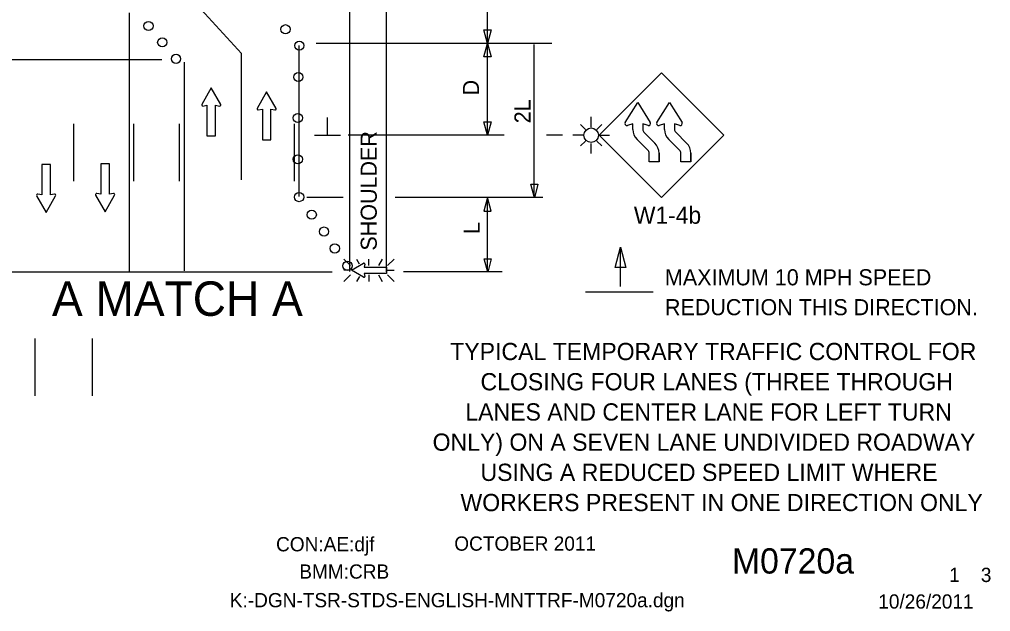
# Model space of a CAD drawing. Extents: x 16726 to 19504, y 5932 to 7446.
# Drawn here: x 16978.9 to 17401.8, y 5931.8 to 6189.6 of the extents above; entities that cross this region are included whole.
import ezdxf

# ---------------------------------------------------------------- set-up
doc = ezdxf.new("R2010")
doc.units = 0
for name, color, linetype in [('ALI_LEGAL_EX', 7, 'Continuous'), ('BORDER_SIGNAL_WO', 7, 'Continuous'), ('MT_SCRATCH_LEVEL_E', 7, 'Continuous'), ('PAVT_EDGE_EX', 7, 'Continuous'), ('TRAFFIC_SIGNS_PR', 7, 'Continuous'), ('TYPICAL_TEXT_DIMEN_PR', 7, 'Continuous')]:
    doc.layers.add(name, color=color, linetype=linetype)

msp = doc.modelspace()

# ---------------------------------------------------------------- linework, layer by layer
at = {"layer": 'ALI_LEGAL_EX'}
for points in [[(17075.62, 6119.76), (17075.62, 6174.72)], [(17002.71, 6119.12), (17002.71, 6144.12)], [(17028.71, 6119.12), (17028.71, 6144.12)], [(17048.71, 6119.12), (17048.71, 6144.12)], [(17098.71, 6119.12), (17098.71, 6144.12)]]:
    msp.add_lwpolyline(points, dxfattribs=at)
at = {"layer": 'MT_SCRATCH_LEVEL_E'}
for p, q in [((17062.47, 6159.81), (17058.36, 6152.57)), ((17062.47, 6159.81), (17058.36, 6152.57)), ((17066.62, 6152.57), (17062.47, 6159.81)), ((17066.62, 6152.57), (17062.47, 6159.81)), ((17086.57, 6158.1), (17082.46, 6150.86)), ((17086.57, 6158.1), (17082.46, 6150.86)), ((17090.72, 6150.86), (17086.57, 6158.1)), ((17090.72, 6150.86), (17086.57, 6158.1)), ((17058.85, 6151.89), (17060.62, 6152.2)), ((17058.85, 6151.89), (17060.62, 6152.2)), ((17060.62, 6152.2), (17060.62, 6138.94)), ((17060.62, 6152.2), (17060.62, 6138.94)), ((17064.36, 6138.94), (17064.36, 6152.2)), ((17064.36, 6152.2), (17066.14, 6151.89)), ((17064.36, 6138.94), (17064.36, 6152.2)), ((17064.36, 6152.2), (17066.14, 6151.89)), ((17082.94, 6150.17), (17084.72, 6150.49)), ((17082.94, 6150.17), (17084.72, 6150.49)), ((17084.72, 6150.49), (17084.72, 6137.23)), ((17084.72, 6150.49), (17084.72, 6137.23)), ((17088.46, 6137.23), (17088.46, 6150.49)), ((17088.46, 6150.49), (17090.24, 6150.17)), ((17088.46, 6137.23), (17088.46, 6150.49)), ((17088.46, 6150.49), (17090.24, 6150.17)), ((17060.62, 6138.94), (17064.36, 6138.94)), ((17060.62, 6138.94), (17064.36, 6138.94)), ((17084.72, 6137.23), (17088.46, 6137.23)), ((17084.72, 6137.23), (17088.46, 6137.23)), ((16992.45, 6126.46), (16988.71, 6126.46)), ((16988.71, 6126.46), (16988.71, 6113.2)), ((16992.45, 6126.46), (16988.71, 6126.46)), ((16988.71, 6126.46), (16988.71, 6113.2)), ((16992.45, 6113.2), (16992.45, 6126.46)), ((16992.45, 6113.2), (16992.45, 6126.46)), ((17018.13, 6126.72), (17014.39, 6126.72)), ((17014.39, 6126.72), (17014.39, 6113.46)), ((17018.13, 6126.72), (17014.39, 6126.72)), ((17014.39, 6126.72), (17014.39, 6113.46)), ((17018.13, 6113.46), (17018.13, 6126.72)), ((17018.13, 6113.46), (17018.13, 6126.72)), ((16986.45, 6112.84), (16990.6, 6105.6)), ((16986.45, 6112.84), (16990.6, 6105.6)), ((16988.71, 6113.2), (16986.93, 6113.52)), ((16988.71, 6113.2), (16986.93, 6113.52)), ((16990.6, 6105.6), (16994.71, 6112.84)), ((16990.6, 6105.6), (16994.71, 6112.84)), ((16994.23, 6113.52), (16992.45, 6113.2)), ((16994.23, 6113.52), (16992.45, 6113.2)), ((17012.13, 6113.09), (17016.28, 6105.85)), ((17012.13, 6113.09), (17016.28, 6105.85)), ((17014.39, 6113.46), (17012.61, 6113.78)), ((17014.39, 6113.46), (17012.61, 6113.78)), ((17016.28, 6105.85), (17020.39, 6113.09)), ((17016.28, 6105.85), (17020.39, 6113.09)), ((17019.91, 6113.78), (17018.13, 6113.46)), ((17019.91, 6113.78), (17018.13, 6113.46))]:
    msp.add_line(p, q, dxfattribs=at)
for centre, start, end in [((17058.77, 6152.35), 150.4248, 279.9638), ((17058.77, 6152.35), 150.4248, 279.9638), ((17066.21, 6152.35), 260.0362, 29.7731), ((17066.21, 6152.35), 260.0362, 29.7731), ((17082.87, 6150.63), 150.4248, 279.9638), ((17082.87, 6150.63), 150.4248, 279.9638), ((17090.31, 6150.63), 260.0362, 29.7731), ((17090.31, 6150.63), 260.0362, 29.7731), ((16986.86, 6113.06), 80.0362, 209.7731), ((16986.86, 6113.06), 80.0362, 209.7731), ((16994.3, 6113.06), 330.4248, 99.9638), ((16994.3, 6113.06), 330.4248, 99.9638), ((17012.54, 6113.32), 80.0362, 209.7731), ((17012.54, 6113.32), 80.0362, 209.7731), ((17019.98, 6113.32), 330.4248, 99.9638), ((17019.98, 6113.32), 330.4248, 99.9638)]:
    msp.add_arc(centre, 0.463, start, end, dxfattribs=at)
at = {"layer": 'PAVT_EDGE_EX'}
for p, q in [((17122.71, 6865.32), (17122.71, 6079.93)), ((17138.71, 6865.32), (17138.71, 6112.72)), ((17026.71, 6192.44), (17026.71, 6079.72)), ((17050.71, 6170.95), (17050.71, 6080.14)), ((17138.71, 6112.72), (17138.71, 6079.72))]:
    msp.add_line(p, q, dxfattribs=at)
for points in [[(16985.78, 6025.74), (16985.78, 6050.74)], [(16985.78, 6025.74), (16985.78, 6050.74)], [(17010.78, 6025.74), (17010.78, 6050.74)], [(17010.78, 6025.74), (17010.78, 6050.74)]]:
    msp.add_lwpolyline(points, dxfattribs=at)
at = {"layer": 'TRAFFIC_SIGNS_PR'}
for p, q in [((17231.4, 6139.23), (17258.55, 6166.38)), ((17258.55, 6166.38), (17285.7, 6139.23)), ((17227.91, 6142.73), (17227.91, 6147.23)), ((17225.4, 6141.69), (17223.29, 6143.8)), ((17230.43, 6141.69), (17232.53, 6143.8)), ((17255.62, 6135.76), (17250.91, 6140.47)), ((17250.91, 6140.47), (17255.62, 6135.76)), ((17269.42, 6135.76), (17264.7, 6140.47)), ((17264.7, 6140.47), (17269.42, 6135.76)), ((17224.76, 6139.18), (17219.92, 6139.18)), ((17225.4, 6136.66), (17223.29, 6134.56)), ((17230.43, 6136.66), (17232.53, 6134.56)), ((17231.07, 6139.18), (17235.95, 6139.18)), ((17258.55, 6112.07), (17231.4, 6139.23)), ((17252.57, 6132.71), (17247.86, 6137.42)), ((17252.57, 6132.71), (17247.86, 6137.42)), ((17285.7, 6139.23), (17258.55, 6112.07)), ((17266.37, 6132.71), (17261.65, 6137.42)), ((17266.36, 6132.71), (17261.65, 6137.42)), ((17227.91, 6131.21), (17227.91, 6135.62)), ((17253.17, 6127.64), (17253.17, 6131.34)), ((17257.49, 6127.64), (17253.17, 6127.64)), ((17257.49, 6127.64), (17257.49, 6131.34)), ((17266.97, 6127.64), (17266.97, 6131.34)), ((17271.28, 6127.64), (17266.97, 6127.64)), ((17271.28, 6127.64), (17271.28, 6131.34)), ((17120.25, 6085.24), (17123.07, 6082.42)), ((17125.69, 6085.24), (17126.89, 6083.15)), ((17131.15, 6082.42), (17131.15, 6085.24)), ((17136.94, 6085.24), (17135.31, 6082.42)), ((17139.24, 6082.42), (17142.06, 6085.24)), ((17123.07, 6080.39), (17120.25, 6080.39)), ((17120.25, 6075.54), (17123.07, 6078.36)), ((17126.97, 6077.72), (17125.71, 6075.54)), ((17131.15, 6078.36), (17131.15, 6075.54)), ((17135.29, 6078.36), (17136.92, 6075.54)), ((17139.24, 6080.39), (17142.06, 6080.39)), ((17139.24, 6078.36), (17142.06, 6075.54))]:
    msp.add_line(p, q, dxfattribs=at)
for points in [[(17242.7, 6144.75), (17248.18, 6153.36), (17253.66, 6144.75)], [(17242.7, 6144.75), (17248.18, 6153.36), (17253.66, 6144.75)], [(17256.5, 6144.75), (17261.98, 6153.36), (17267.46, 6144.75)], [(17256.5, 6144.75), (17261.98, 6153.36), (17267.46, 6144.75)], [(17246.03, 6141.73), (17246.03, 6144.1), (17243.66, 6143.45)], [(17246.03, 6141.73), (17246.03, 6144.1), (17243.66, 6143.45)], [(17252.7, 6143.45), (17250.34, 6144.1), (17250.35, 6141.8)], [(17252.7, 6143.45), (17251.87, 6143.68), (17250.34, 6144.1), (17250.35, 6141.8)], [(17259.83, 6141.73), (17259.82, 6144.1), (17257.46, 6143.45)], [(17259.83, 6141.73), (17259.82, 6144.1), (17257.46, 6143.45)], [(17266.5, 6143.45), (17264.14, 6144.1), (17264.14, 6141.8)], [(17266.5, 6143.45), (17265.67, 6143.68), (17264.14, 6144.1), (17264.14, 6141.8)], [(17257.49, 6131.34), (17257.49, 6127.64), (17253.17, 6127.64), (17253.17, 6131.34)], [(17271.29, 6131.34), (17271.28, 6127.64), (17266.97, 6127.64), (17266.97, 6131.34)], [(17128.83, 6077.38), (17123.52, 6080.39), (17128.83, 6083.43)], [(17129.33, 6083.07), (17129.1, 6081.78), (17138.82, 6081.78), (17138.82, 6079.03), (17129.1, 6079.03), (17129.33, 6077.73)]]:
    msp.add_lwpolyline(points, dxfattribs=at)
for centre, radius in [((17035.14, 6186.72), 2), ((17094.81, 6185.3), 2), ((17041.14, 6179.58), 2), ((17100.81, 6178.16), 2), ((17047.14, 6172.44), 2), ((17100.41, 6164.49), 2), ((17100.19, 6146.69), 2), ((17227.91, 6139.18), 3.15), ((17100.19, 6128.69), 2), ((17100.73, 6112.25), 2), ((17106.24, 6104.59), 2), ((17111.58, 6097.24), 2), ((17116.26, 6089.9), 2), ((17121.82, 6082.34), 2)]:
    msp.add_circle(centre, radius, dxfattribs=at)
for centre, radius, start, end in [((17243.43, 6144.29), 0.866, 147.7292, 285.3172), ((17243.43, 6144.29), 0.866, 147.7196, 285.3201), ((17233.59, 6150.54), 10.8, 327.5335, 327.5431), ((17252.93, 6144.28), 0.866, 254.6148, 32.4712), ((17252.93, 6144.28), 0.864, 254.6014, 32.4796), ((17257.23, 6144.29), 0.866, 147.7292, 285.3172), ((17257.23, 6144.29), 0.866, 147.7196, 285.3201), ((17247.39, 6150.54), 10.8, 327.5335, 327.5431), ((17266.73, 6144.28), 0.864, 254.6014, 32.4796), ((17266.73, 6144.28), 0.866, 254.6148, 32.4712), ((17246.52, 6133.03), 10.8, 105.3192, 105.32), ((17252.2, 6141.8), 6.17, 180.6181, 225.7875), ((17252.2, 6141.8), 6.17, 180.6245, 225.2313), ((17252.2, 6141.8), 1.85, 180, 225.7875), ((17252.2, 6141.8), 1.85, 179.8762, 225.7877), ((17260.31, 6133.03), 10.8, 105.3192, 105.32), ((17265.99, 6141.8), 6.17, 180.6181, 225.7875), ((17265.99, 6141.8), 6.17, 180.6245, 225.2313), ((17265.99, 6141.8), 1.85, 180, 225.7875), ((17265.99, 6141.8), 1.85, 179.8762, 225.7877), ((17251.32, 6131.34), 1.85, 0, 47.628), ((17251.32, 6131.34), 1.85, 0, 45.7875), ((17251.32, 6131.34), 6.17, 0, 45.7875), ((17251.32, 6131.34), 6.17, 0, 45.7875), ((17251.32, 6131.34), 6.17, 0, 45.7883), ((17265.12, 6131.34), 1.85, 0, 47.628), ((17265.12, 6131.34), 1.85, 0, 45.7875), ((17265.12, 6131.34), 6.17, 0, 45.7875), ((17265.12, 6131.34), 6.17, 0, 45.7875), ((17265.12, 6131.34), 6.17, 0, 45.7883), ((17128.99, 6083.13), 0.341, 350.0407, 118.5167), ((17128.99, 6077.67), 0.341, 241.1084, 9.2692)]:
    msp.add_arc(centre, radius, start, end, dxfattribs=at)
at = {"layer": 'TYPICAL_TEXT_DIMEN_PR'}
for p, q in [((17182.71, 6179.17), (17182.71, 6267.12)), ((17002.71, 6254.65), (17075.64, 6174.71)), ((17182.74, 6179.15), (17181.17, 6185.02)), ((17181.17, 6185.02), (17182.74, 6185.02)), ((17182.74, 6185.02), (17184.31, 6185.02)), ((17184.31, 6185.02), (17182.74, 6179.15)), ((17100.6, 6178.28), (17100.6, 6112.56)), ((17210.8, 6179.15), (17108.13, 6179.15)), ((17181.17, 6173.31), (17182.74, 6179.17)), ((17182.74, 6179.17), (17184.31, 6173.31)), ((17182.75, 6139.15), (17182.75, 6179.15)), ((17203.14, 6112.66), (17203.14, 6178.73)), ((16893.7, 6172.07), (17040.9, 6172.07)), ((17182.74, 6173.31), (17181.17, 6173.31)), ((17184.31, 6173.31), (17182.74, 6173.31)), ((17113.12, 6139.1), (17113.12, 6146.88)), ((17182.75, 6139.15), (17181.18, 6145.01)), ((17181.18, 6145.01), (17182.75, 6145.01)), ((17182.75, 6145.01), (17184.32, 6145.01)), ((17184.32, 6145.01), (17182.75, 6139.15)), ((17118.74, 6139.1), (17107.49, 6139.1)), ((17189.98, 6139.15), (17122.03, 6139.15)), ((17215.4, 6139.15), (17208.49, 6139.15)), ((17203.18, 6111.98), (17201.61, 6117.84)), ((17201.61, 6117.84), (17203.18, 6117.84)), ((17203.18, 6117.84), (17204.75, 6117.84)), ((17204.75, 6117.84), (17203.18, 6111.98)), ((17119.91, 6112.01), (17104.16, 6112.01)), ((17206.84, 6112.01), (17142.6, 6112.01)), ((17182.75, 6112.01), (17181.18, 6106.15)), ((17182.71, 6090.25), (17182.71, 6111.5)), ((17182.73, 6079.65), (17182.73, 6111.93)), ((17184.32, 6106.15), (17182.75, 6112.01)), ((17181.18, 6106.15), (17182.75, 6106.15)), ((17182.75, 6106.15), (17184.32, 6106.15)), ((17238.32, 6081.66), (17240.67, 6090.45)), ((17240.67, 6073.33), (17240.67, 6090.45)), ((17240.67, 6090.45), (17243.03, 6081.66)), ((17182.86, 6079.57), (17181.29, 6085.43)), ((17181.29, 6085.43), (17182.86, 6085.43)), ((17182.86, 6085.43), (17184.43, 6085.43)), ((17184.43, 6085.43), (17182.86, 6079.57)), ((17240.67, 6081.66), (17238.32, 6081.66)), ((17243.03, 6081.66), (17240.67, 6081.66)), ((16927.17, 6079.72), (17115.16, 6079.72)), ((17189.17, 6079.72), (17146.21, 6079.72)), ((17254.85, 6070.83), (17225.41, 6070.83))]:
    msp.add_line(p, q, dxfattribs=at)

# ---------------------------------------------------------------- texts
at = {"layer": 'BORDER_SIGNAL_WO'}
for s, height, p in [('TYPICAL TEMPORARY TRAFFIC CONTROL FOR ', 7.5024, (17166.54, 6041.29)), ('CLOSING FOUR LANES (THREE THROUGH ', 7.5024, (17179.72, 6028.14)), ('LANES AND CENTER LANE FOR LEFT TURN ', 7.5024, (17173.13, 6014.99)), ('ONLY) ON A SEVEN LANE UNDIVIDED ROADWAY ', 7.5024, (17158.86, 6001.84)), ('USING A REDUCED SPEED LIMIT WHERE ', 7.5024, (17179.72, 5988.7)), ('WORKERS PRESENT IN ONE DIRECTION ONLY', 7.5024, (17171, 5975.55)), ('CON:AE:djf', 6.2, (17090.69, 5958.06)), ('    OCTOBER 2011    ', 6.2, (17159.08, 5958.34)), ('    M0720a   ', 11, (17272.86, 5948.38)), ('BMM:CRB   ', 6.2, (17100.81, 5946.17)), (' 1    3 ', 6.2, (17381.45, 5944.7)), ('K:-DGN-TSR-STDS-ENGLISH-MNTTRF-M0720a.dgn        ', 6.2, (17070.55, 5933.71)), ('10/26/2011    ', 6.2, (17352.93, 5933.13))]:
    msp.add_text(s, height=height, dxfattribs=at).set_placement(p)
at = {"layer": 'TRAFFIC_SIGNS_PR'}
msp.add_text('W1-4b', height=7.44, dxfattribs=at).set_placement((17246.5, 6100.63))
at = {"layer": 'TYPICAL_TEXT_DIMEN_PR'}
for s, p in [('D', (17179.06, 6156.5)), ('2L', (17201.5, 6144.35)), ('SHOULDER', (17134.55, 6088.95)), ('L', (17179.37, 6096.15))]:
    msp.add_text(s, height=7, rotation=90, dxfattribs=at).set_placement(p)
for s, height, p in [('MAXIMUM 10 MPH SPEED', 7, (17260.03, 6073.84)), ('A MATCH A', 15, (16993.12, 6060.55)), ('REDUCTION THIS DIRECTION.', 7, (17260.03, 6060.84))]:
    msp.add_text(s, height=height, dxfattribs=at).set_placement(p)

doc.saveas('drawing.dxf')
